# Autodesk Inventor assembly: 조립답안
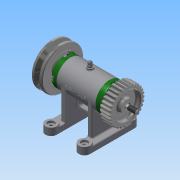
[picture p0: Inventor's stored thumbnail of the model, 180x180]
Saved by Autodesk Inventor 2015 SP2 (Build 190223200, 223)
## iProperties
Created: 2015-11
Part Number: 조립답안
Document SubType Name: Assembly
Designer: AMC
Author: AMC
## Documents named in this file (14)
- C:\Users\AMC\Desktop\451109V1024\조립답안.iam
- C:\Users\AMC\Desktop\451109V1024\본체.ipt
- C:\Users\AMC\Desktop\451109V1024\커버.ipt
- C:\Users\AMC\Desktop\451109V1024\축.ipt
- C:\Users\AMC\Desktop\451109V1024\베어링 15 x 32 x 9.ipt
- C:\Users\AMC\Desktop\451109V1024\오일 실 15 25 7.ipt
- C:\Users\AMC\Desktop\451109V1024\스퍼기어.ipt
- C:\Users\AMC\Desktop\451109V1024\키 3 x 3 x 12.ipt
- C:\Users\AMC\Desktop\451109V1024\스프링와셔 8.ipt
- C:\Users\AMC\Desktop\451109V1024\V벨트풀리.ipt
- C:\Users\AMC\Desktop\451109V1024\너트 M 8.ipt
- C:\Users\AMC\Desktop\451109V1024\와셔 8x17.ipt
- C:\Users\AMC\Desktop\451109V1024\볼트 M4 x 12.ipt
- C:\Users\AMC\Desktop\451109V1024\니플 M 6 x 0.75.ipt
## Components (11 placed, 3 different names)
1. KS B 2023 6002 - 15 x 32 x 9:1
2. KS B 2023 6002 - 15 x 32 x 9:2
3. V벨트풀리:1
4. ISO 4762 M4 x 12:2
5. ISO 4762 M4 x 12:3
6. ISO 4762 M4 x 12:4
7. ISO 4762 M4 x 12:5
8. ISO 4762 M4 x 12:1
9. ISO 4762 M4 x 12:6
10. ISO 4762 M4 x 12:7
11. ISO 4762 M4 x 12:8
